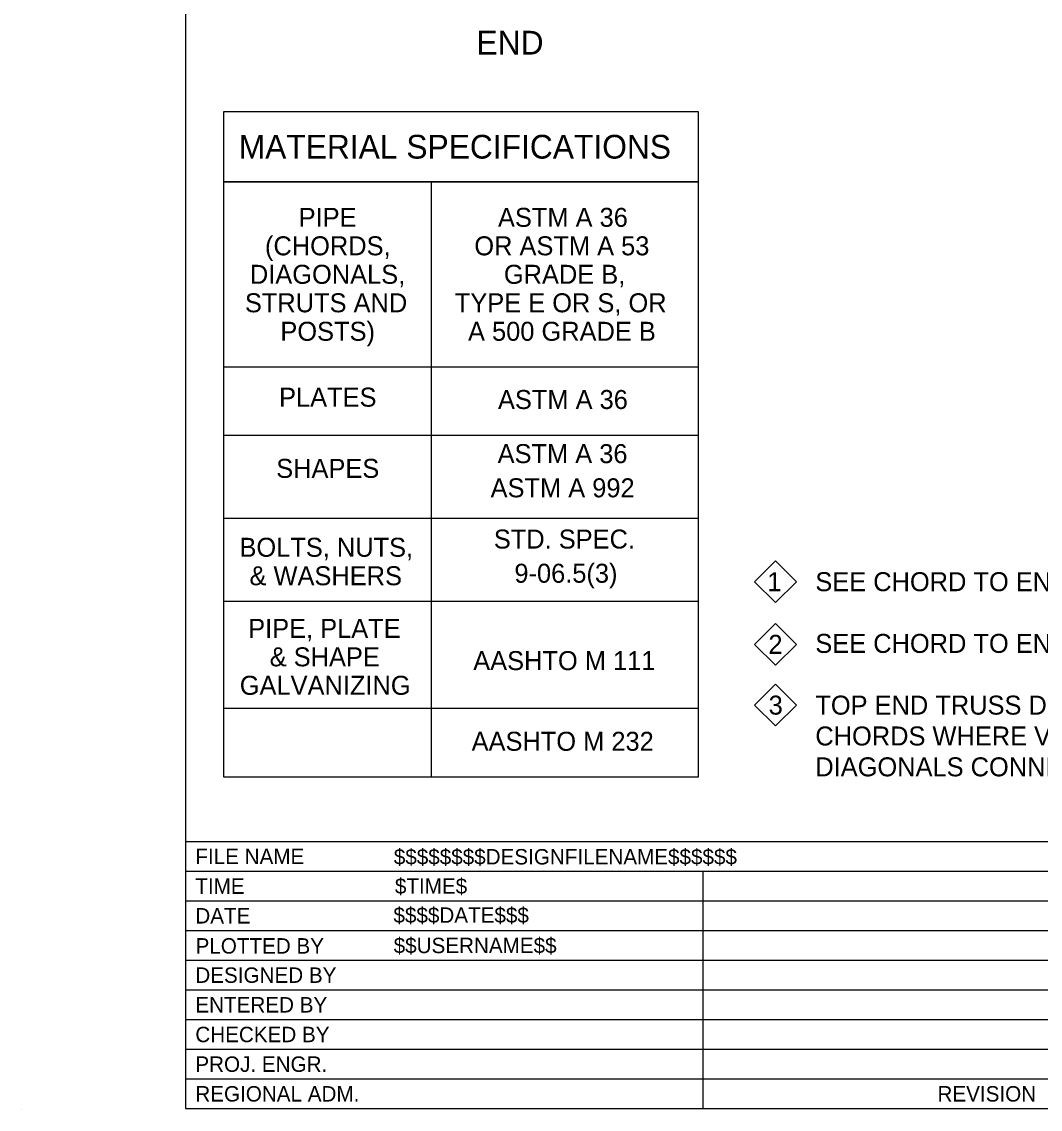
# Model space of a CAD drawing. Extents: x 99862 to 104211, y 98939 to 111076.
# Drawn here: x 99862 to 100720, y 100000 to 100916 of the extents above; entities that cross this region are included whole.
import ezdxf

# ---------------------------------------------------------------- set-up
doc = ezdxf.new("R2010")
doc.units = 0
for name, color, linetype in [('Level 20', 7, 'Continuous'), ('Level 21', 7, 'Continuous'), ('Level 40', 7, 'Continuous'), ('Level 60', 7, 'Continuous')]:
    doc.layers.add(name, color=color, linetype=linetype)

msp = doc.modelspace()

# ---------------------------------------------------------------- linework, layer by layer
at = {"layer": 'Level 20'}
for points in [[(100496.8, 100461.55), (100514.35, 100444), (100496.8, 100426.45), (100479.24, 100444)], [(100496.8, 100408.73), (100514.35, 100391.18), (100496.8, 100373.62), (100479.24, 100391.18)], [(100496.8, 100357.55), (100514.35, 100340), (100496.8, 100322.45), (100479.24, 100340)]]:
    msp.add_lwpolyline(points, close=True, dxfattribs=at)
at = {"layer": 'Level 40'}
for p, q in [((100206.86, 100780.99), (100206.86, 100279.54)), ((100031.86, 100624.99), (100431.86, 100624.99)), ((100031.86, 100567.5), (100431.86, 100567.5)), ((100031.86, 100497.5), (100431.86, 100497.5)), ((100031.86, 100427.5), (100431.86, 100427.5)), ((100031.86, 100337.5), (100431.86, 100337.5))]:
    msp.add_line(p, q, dxfattribs=at)
for points in [[(100031.86, 100780.99), (100431.86, 100780.99), (100431.86, 100839.99), (100031.86, 100839.99)], [(100031.86, 100780.99), (100431.86, 100780.99), (100431.86, 100839.99), (100031.86, 100839.99)], [(100031.86, 100279.54), (100431.86, 100279.54), (100431.86, 100780.99), (100031.86, 100780.99)]]:
    msp.add_lwpolyline(points, close=True, dxfattribs=at)
at = {"layer": 'Level 60'}
for p, q in [((100000, 102075), (100000, 100000)), ((100000, 100225), (103150, 100225)), ((100000, 100200), (101490.14, 100200)), ((100435.46, 100200), (100435.46, 100000)), ((100000, 100175), (100436.08, 100175)), ((100436.08, 100175), (101088.45, 100175)), ((100000, 100150), (100436.08, 100150)), ((100436.08, 100150), (101088.45, 100150)), ((100000, 100125), (101088.45, 100125)), ((100000, 100100), (101088.45, 100100)), ((100000, 100075), (101088.45, 100075)), ((100000, 100050), (101088.45, 100050)), ((100000, 100025), (101088.45, 100025)), ((99862, 99999.5), (99862, 99999.5)), ((100000, 100000), (103150, 100000))]:
    msp.add_line(p, q, dxfattribs=at)

# ---------------------------------------------------------------- texts
at = {"layer": 'Level 20'}
for s, height, p in [('END', 20, (100244.98, 100888.14)), ('MATERIAL SPECIFICATIONS', 20, (100044.71, 100800.49)), ('SEE CHORD TO END POST CONNECTION TYPE', 16, (100530.35, 100436)), ('2', 16, (100490.81, 100383.18)), ('SEE CHORD TO END POST CONNECTION TYPE', 16, (100530.35, 100384)), ('3', 16, (100491.02, 100332)), ('TOP END TRUSS DIAGONAL JOINS END POSTS AT', 16, (100530.35, 100332)), ('CHORDS WHERE VERTICAL AND HORIZONTAL', 16, (100530.35, 100306)), ('DIAGONALS CONNECT', 16, (100530.35, 100280))]:
    msp.add_text(s, height=height, dxfattribs=at).set_placement(p)
msp.add_text('1', height=16, rotation=360, dxfattribs=at).set_placement((100489.93, 100436))
at = {"layer": 'Level 21'}
for s, p in [('PIPE', (100095.21, 100742.99)), ('ASTM A 36', (100263.06, 100742.99)), ('(CHORDS,', (100066.84, 100718.99)), ('OR ASTM A 53', (100243.15, 100718.99)), ('DIAGONALS,', (100054.15, 100694.99)), ('GRADE B,', (100268.04, 100694.99)), ('STRUTS AND', (100049.94, 100670.99)), ('TYPE E OR S, OR', (100226.73, 100670.99)), ('POSTS)', (100079.81, 100646.99)), ('A 500 GRADE B', (100237.85, 100646.99)), ('PLATES', (100078.71, 100591.48)), ('ASTM A 36', (100263.06, 100589.5)), ('ASTM A 36', (100262.76, 100543.9)), ('SHAPES', (100076.3, 100531.48)), ('ASTM A 992', (100256.87, 100515.1)), ('BOLTS, NUTS,', (100045.36, 100465)), ('STD. SPEC.', (100259.57, 100471.92)), ('& WASHERS', (100053.82, 100441)), ('9-06.5(3)', (100276.9, 100443.12)), ('PIPE, PLATE', (100052.7, 100396.69)), ('& SHAPE', (100070.82, 100372.69)), ('AASHTO M 111', (100242.23, 100369.5)), ('GALVANIZING', (100045.61, 100348.69)), ('AASHTO M 232', (100240.87, 100301.54))]:
    msp.add_text(s, height=16, dxfattribs=at).set_placement(p)
at = {"layer": 'Level 60'}
for s, p in [('FILE NAME', (100008.19, 100206)), ('$$$$$$$$DESIGNFILENAME$$$$$$', (100175.35, 100205.73)), ('TIME', (100008.19, 100181)), ('$TIME$', (100176.26, 100181.03)), ('DATE', (100008.19, 100156)), ('$$$$DATE$$$', (100175.04, 100156.58)), ('PLOTTED BY', (100008.37, 100130.65)), ('$$USERNAME$$', (100175.22, 100131.02)), ('DESIGNED BY', (100008.19, 100106)), ('ENTERED BY', (100008.19, 100081)), ('CHECKED BY', (100008.19, 100056)), ('PROJ. ENGR.', (100008.19, 100031)), ('REGIONAL ADM.', (100008.19, 100006)), ('REVISION', (100633.21, 100006))]:
    msp.add_text(s, height=13, dxfattribs=at).set_placement(p)

doc.saveas('drawing.dxf')
